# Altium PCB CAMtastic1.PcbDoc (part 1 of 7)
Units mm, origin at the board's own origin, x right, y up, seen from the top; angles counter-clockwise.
Board outline 150.22 x 135.24 mm, 5 copper layers (Top Layer, Layer 1, Mid-Layer 1, Layer 2, Bottom Layer), stack 0.461 mm thick; 0 components, 362 nets, 2885 pads, 0 vias.
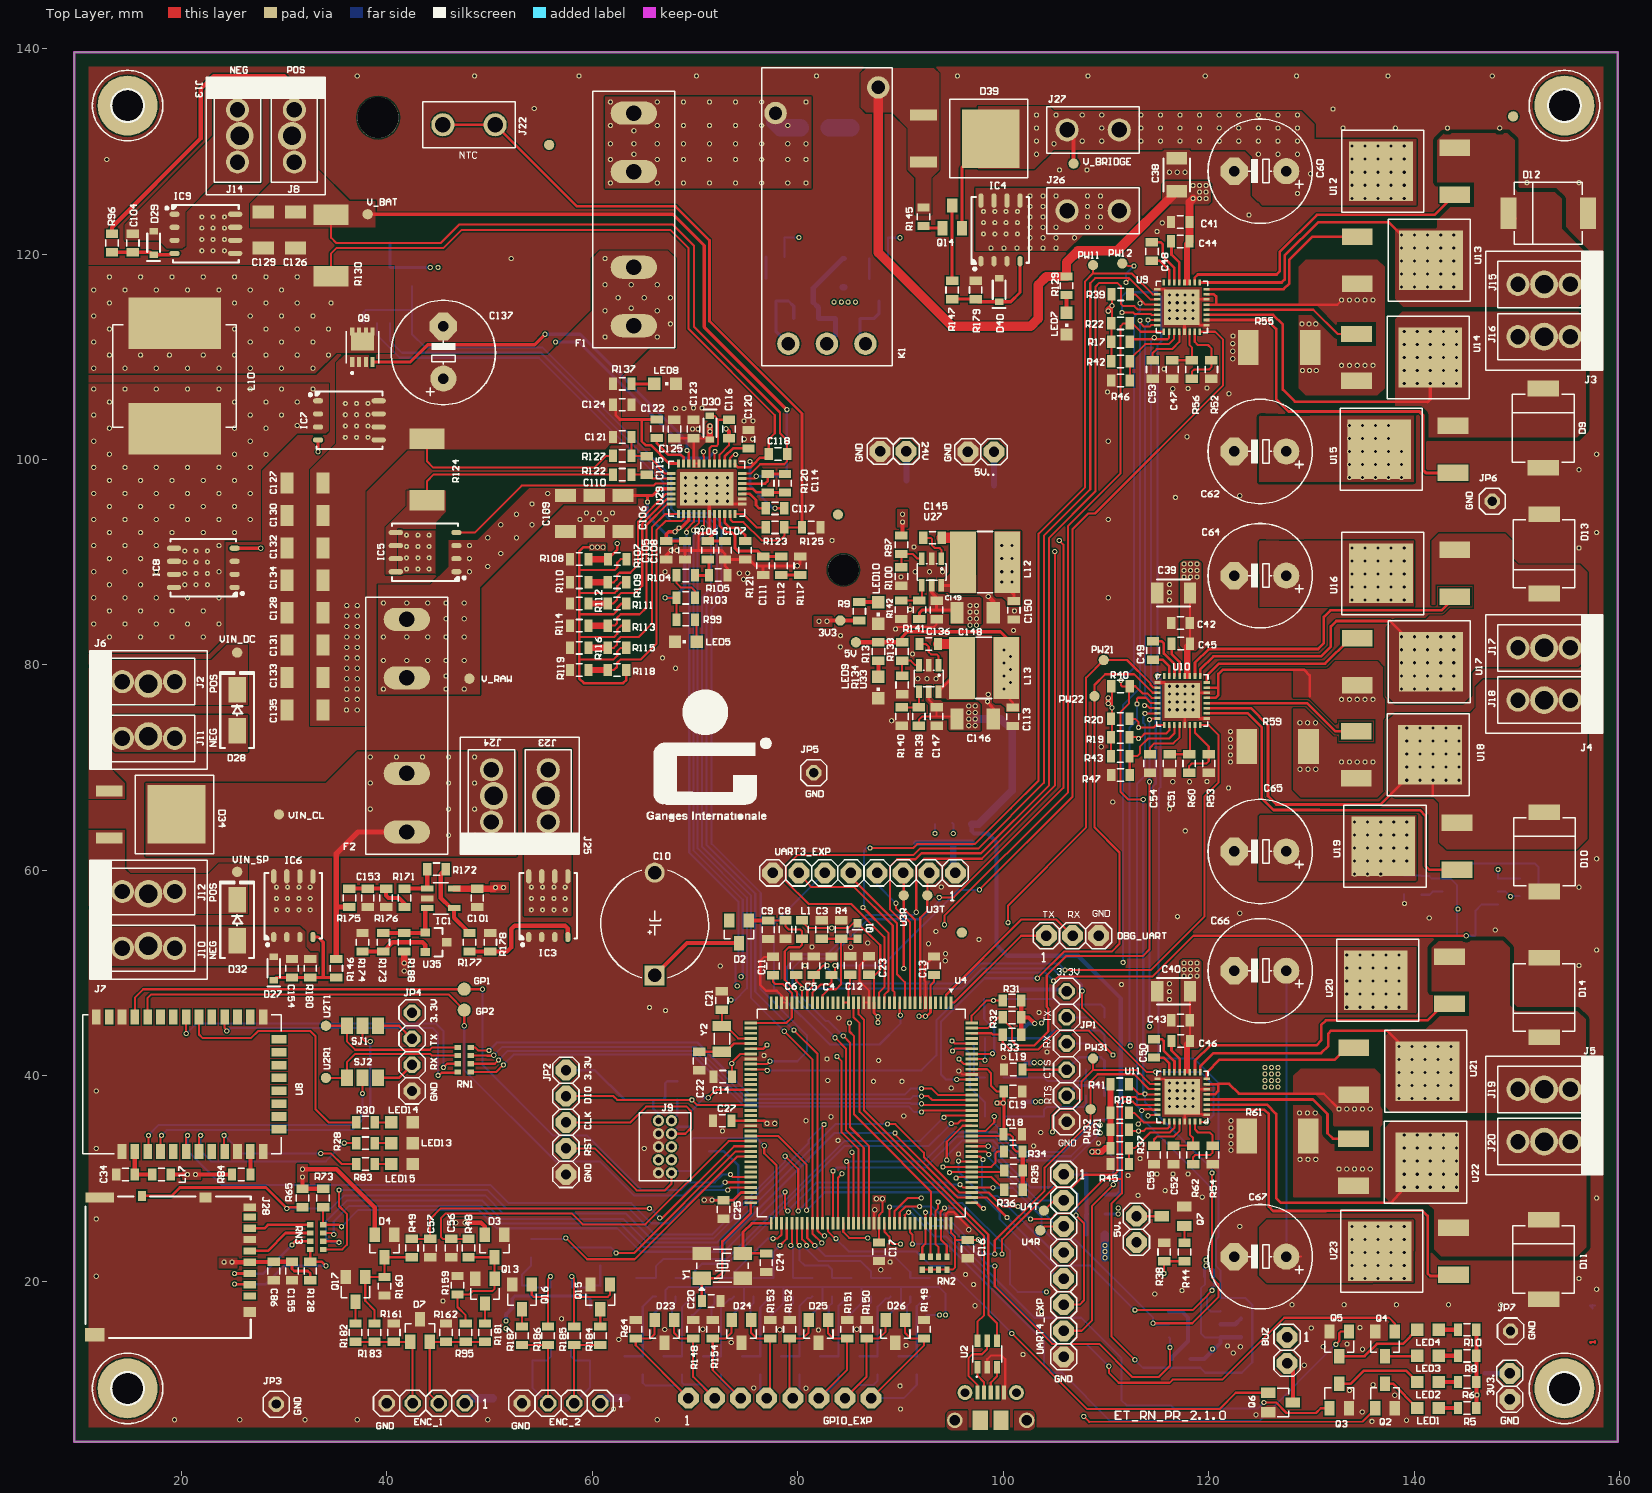
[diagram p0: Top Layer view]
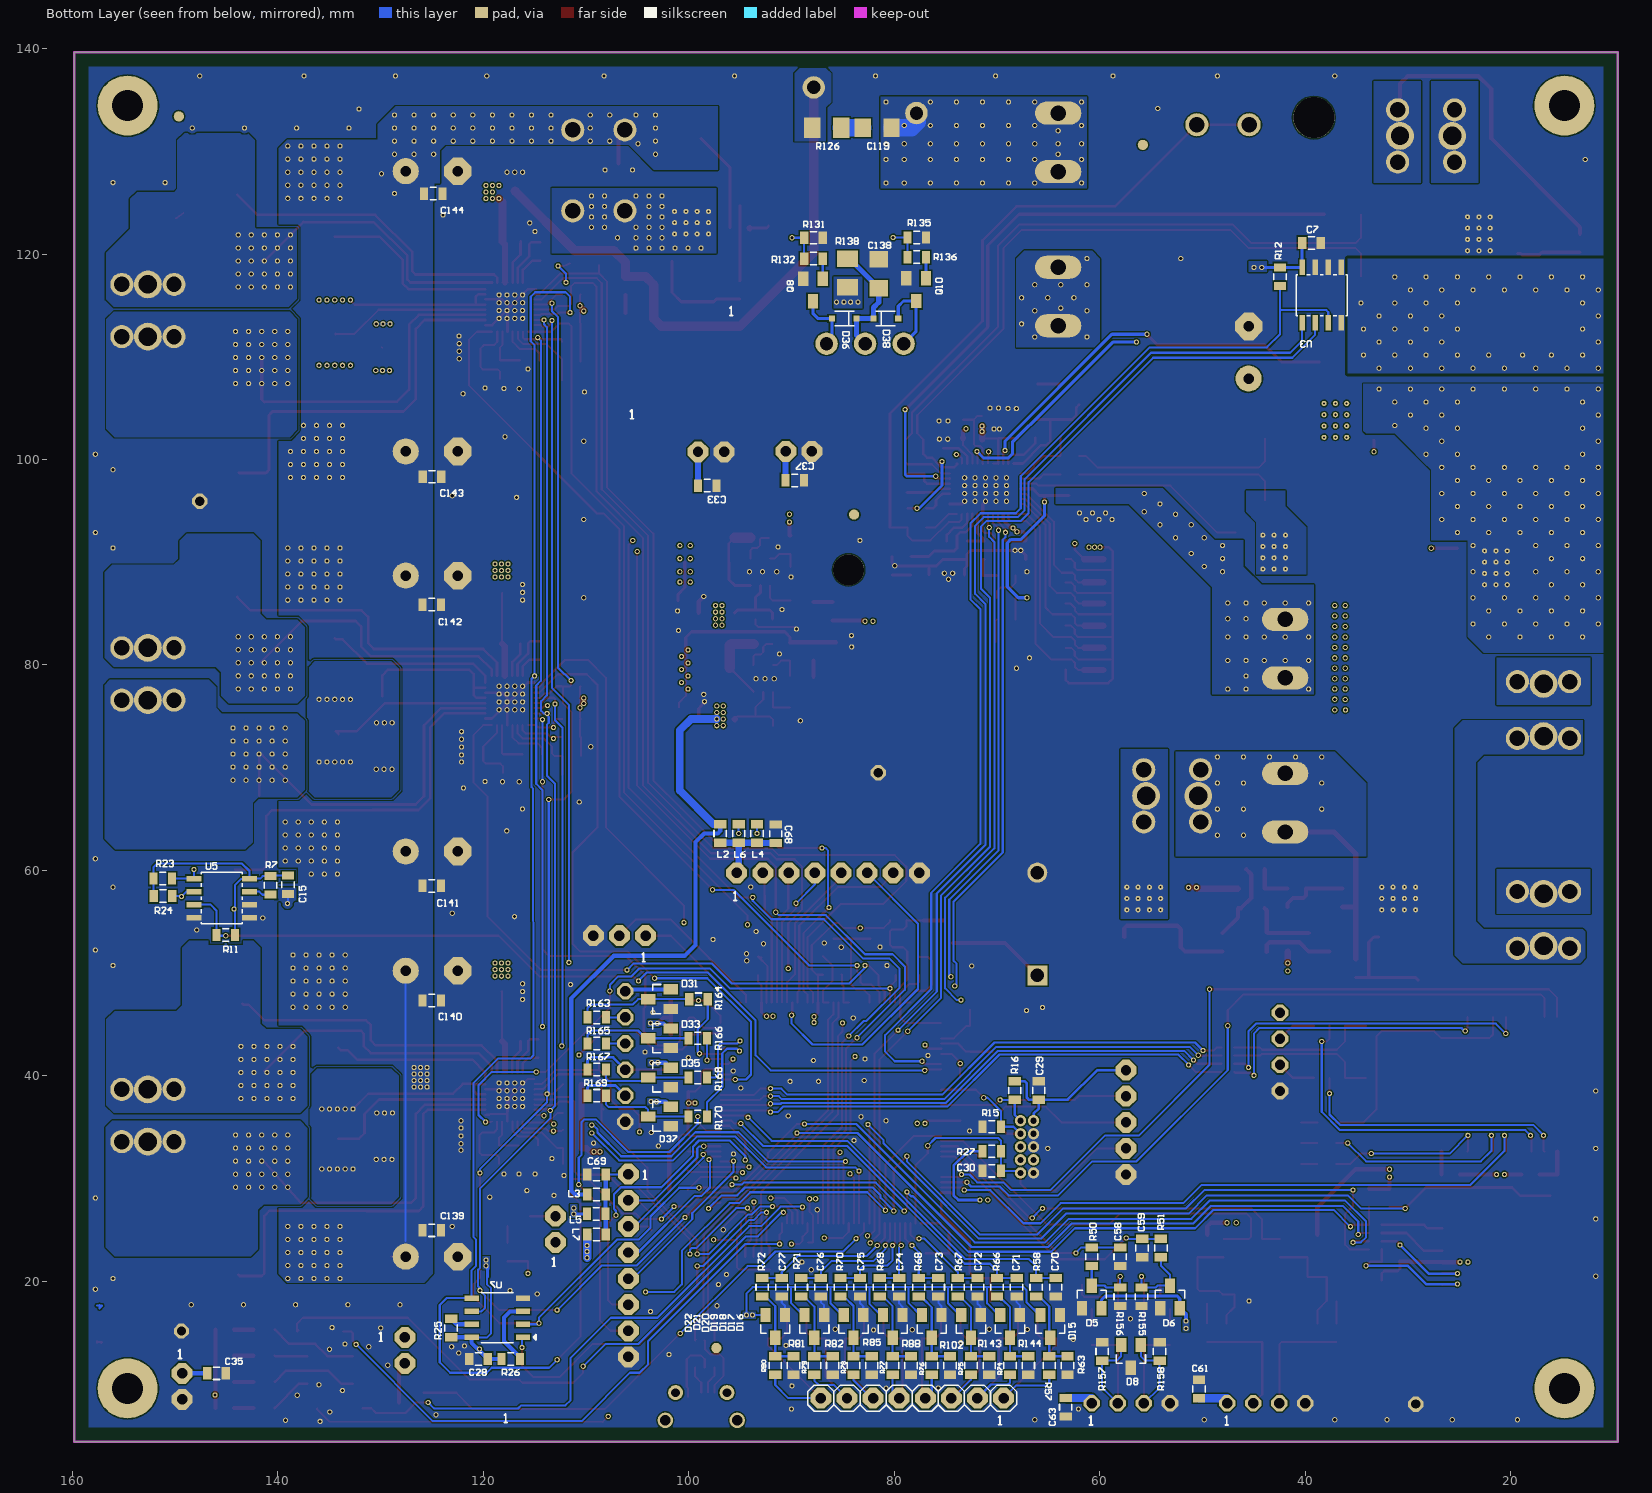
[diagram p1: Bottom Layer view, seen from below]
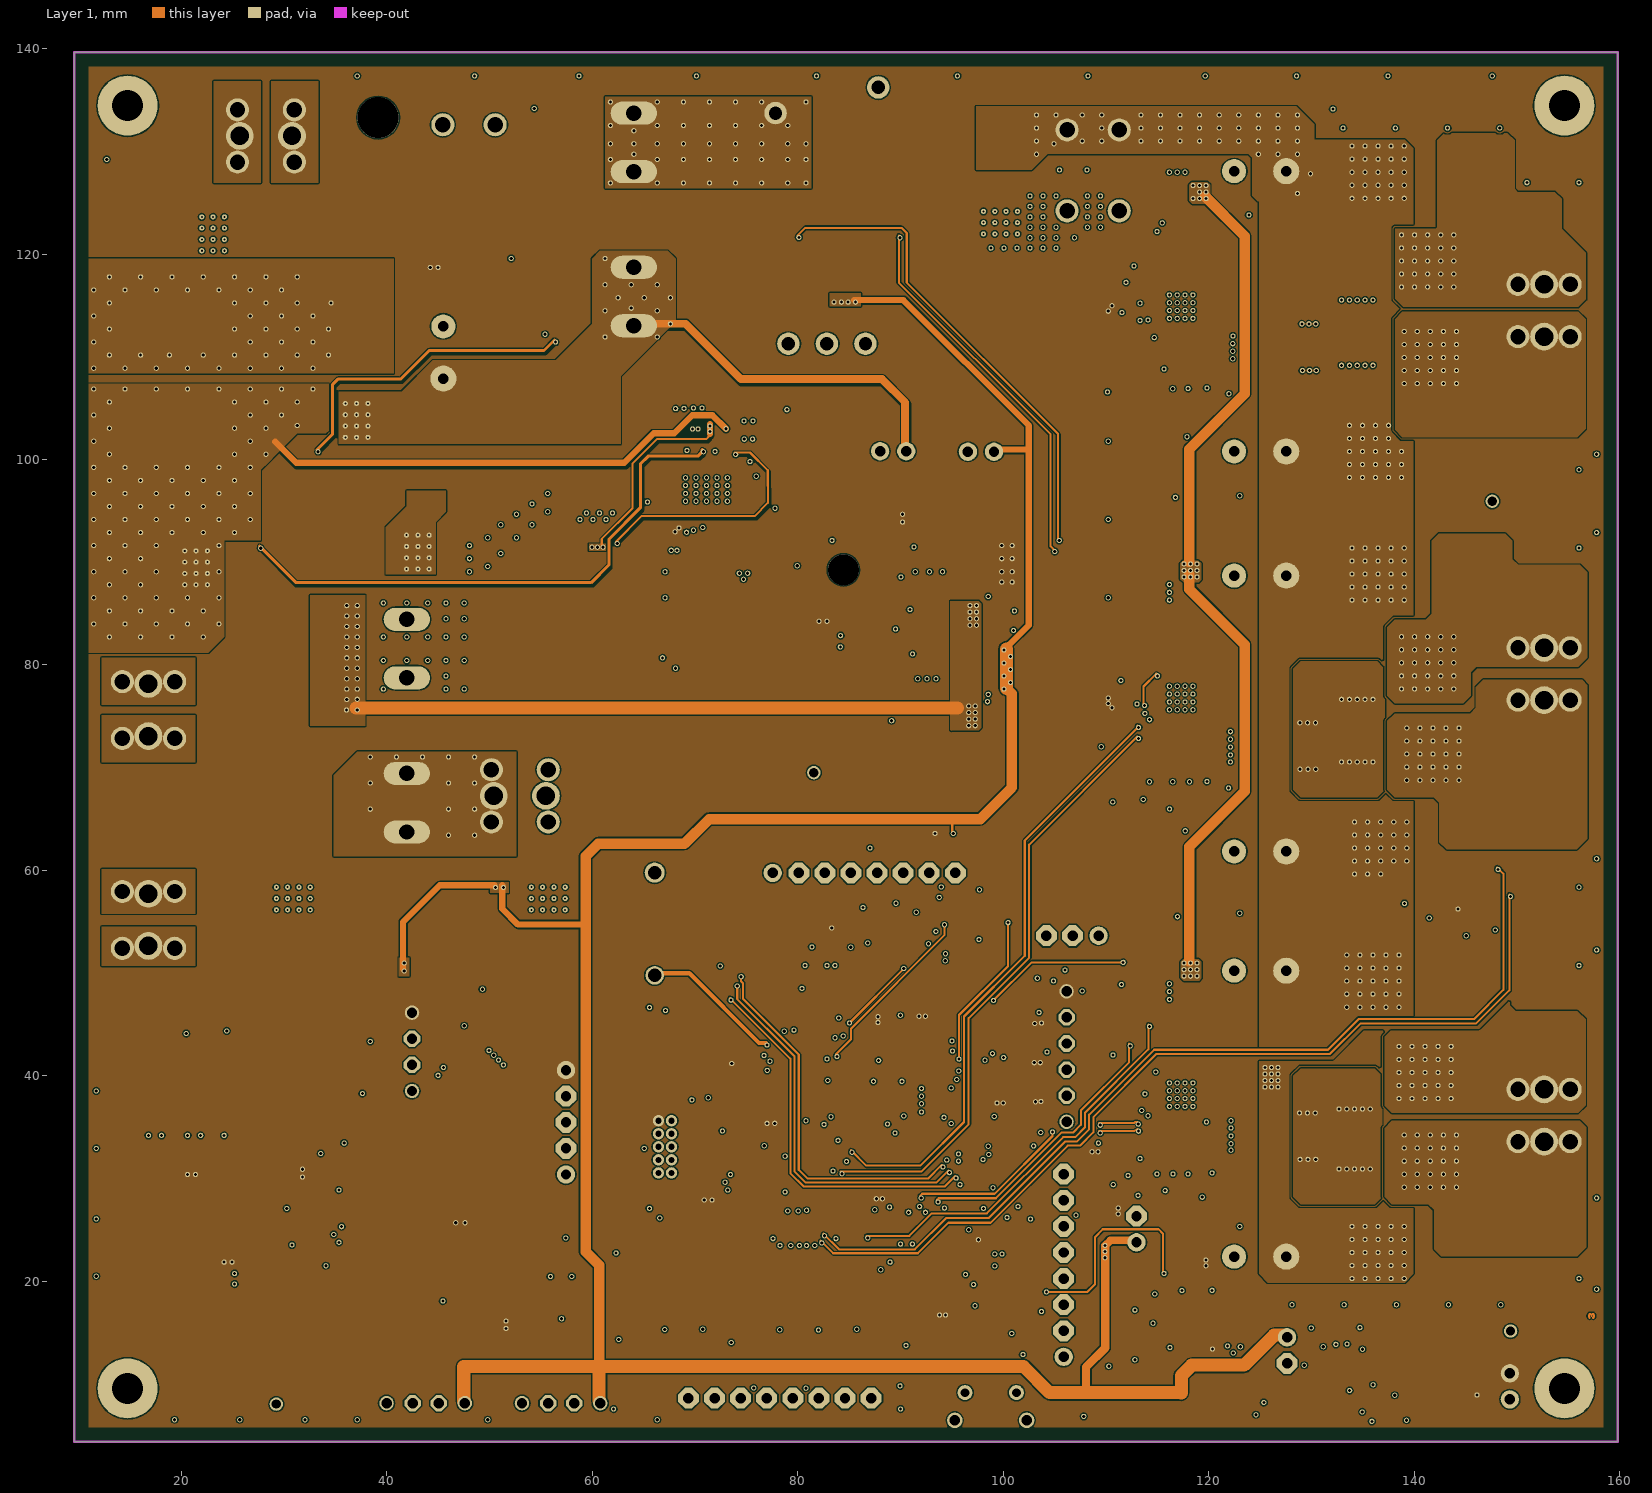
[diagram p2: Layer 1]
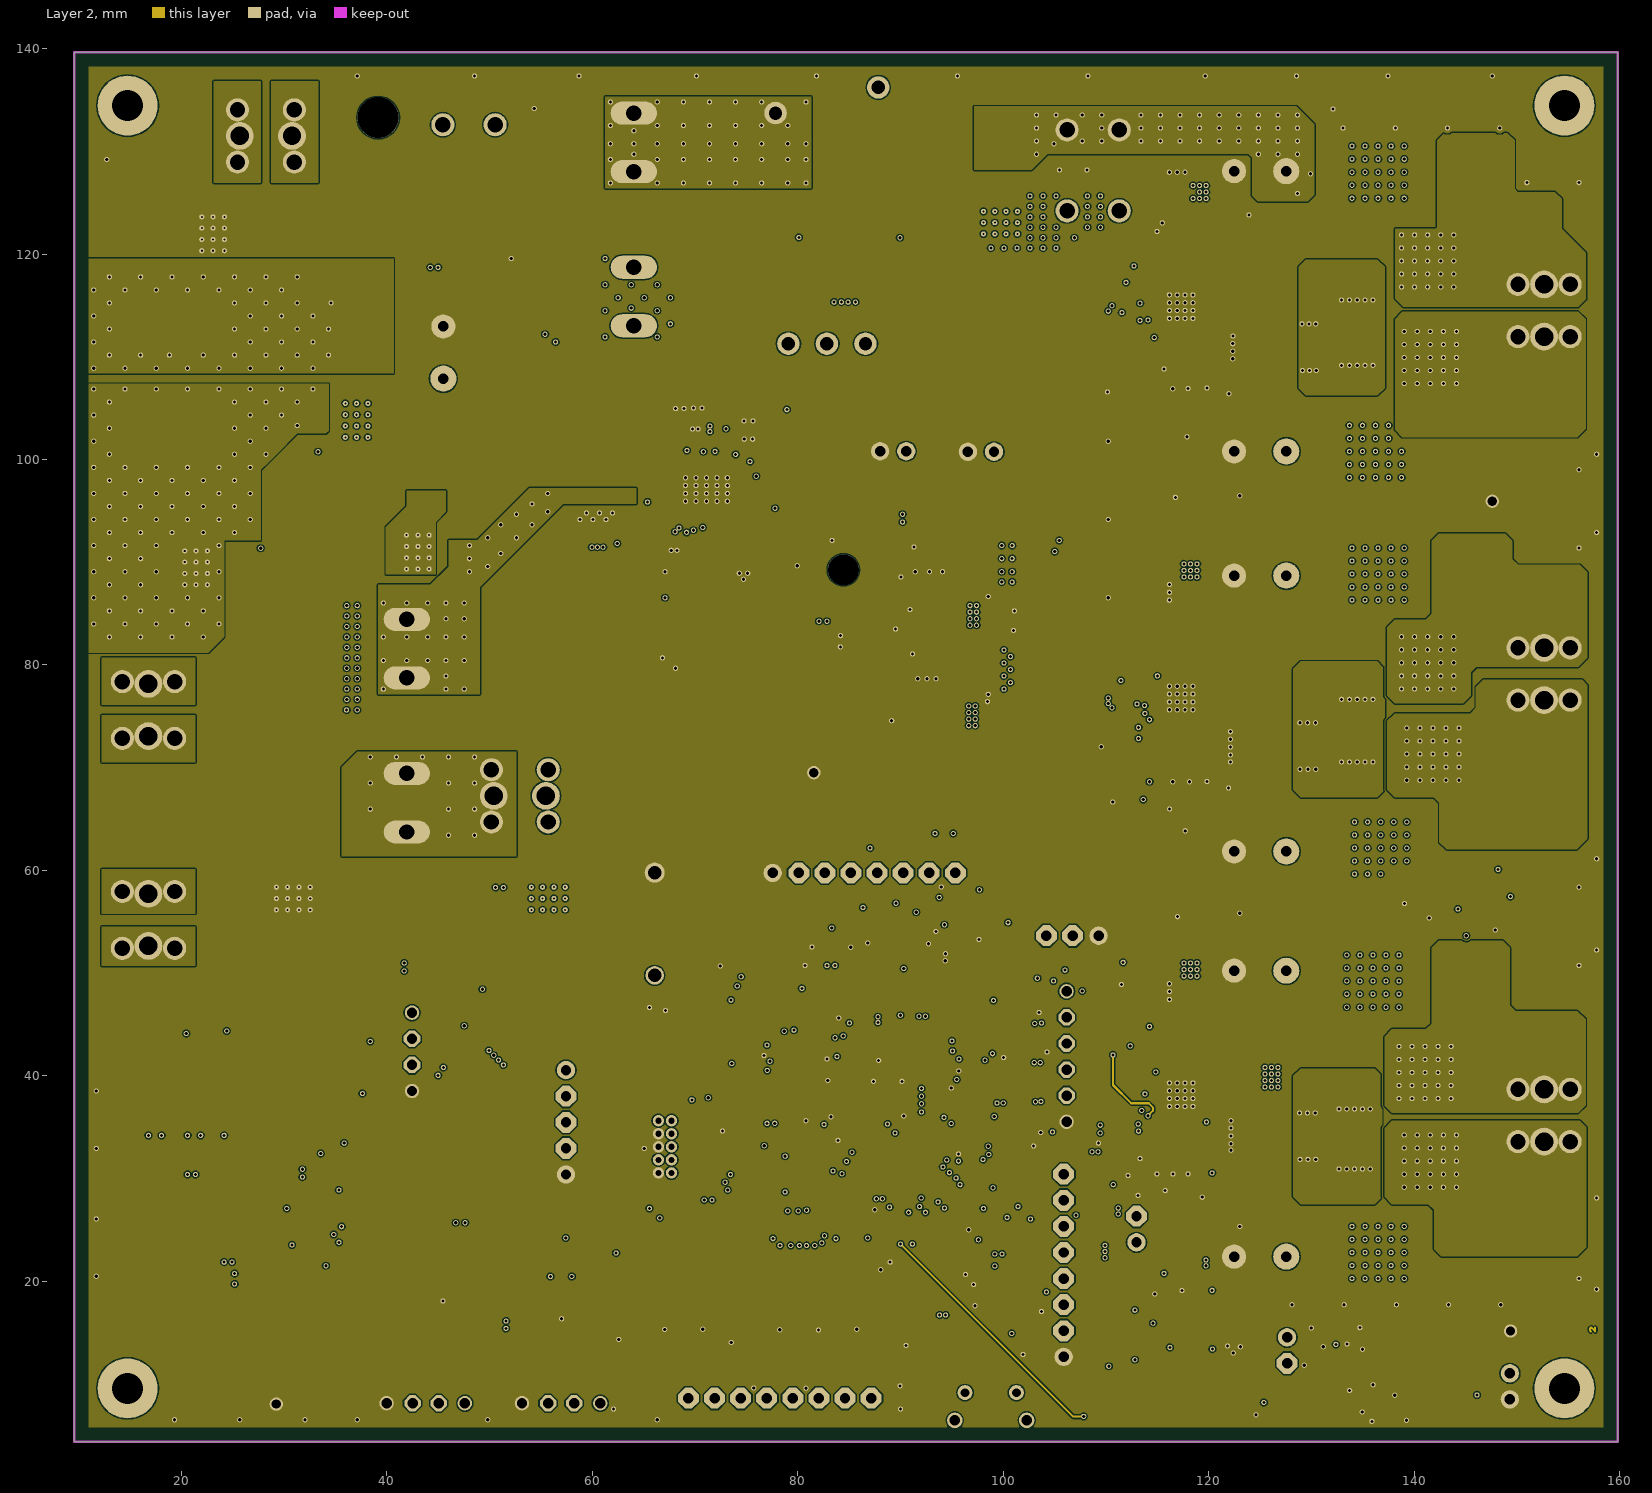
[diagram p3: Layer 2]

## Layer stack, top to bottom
Top Solder: solder mask 0.0102, Solder Resist, Dk 3.5
Top Layer: signal copper 0.0356
Dielectric 2: prepreg 0.0711, PP-006, Dk 4.1
Layer 1: signal copper 0.035
Dielectric 3: prepreg 0.0711, PP-006, Dk 4.1
Mid-Layer 1: signal copper 0.0356
Dielectric 4: prepreg 0.0711, PP-006, Dk 4.1
Layer 2: signal copper 0.035
Dielectric 5: prepreg 0.0711, PP-006, Dk 4.1
Bottom Layer: signal copper 0.0356
Bottom Solder: solder mask 0.0102, Solder Resist, Dk 3.5

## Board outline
9.571,4.394 159.794,4.394 159.794,139.632 9.571,139.632

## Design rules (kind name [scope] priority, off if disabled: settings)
Clearance [All] p1: gap=0.127 ignorepadtopadclearanceinfootprint=FALSE
HoleSize [All] p1: absolutevalues=TRUE maxlimit=4 minlimit=0.025 maxpercent=80.000 minpercent=20.000
HoleToHoleClearance [All] p1: gap=0.2 allowstackedmicrovias=TRUE
MinimumSolderMaskSliver [All] p1: minsoldermaskwidth=0
PolygonConnect CAM_PolygonConnect_$Net220 [InNet('$Net220')] p1: connectstyle=Direct reliefconductorwidth=0.254 reliefentries=4 polygonreliefangle="90 Angle" airgapwidth=0.254
PolygonConnect CAM_PolygonConnect_$Net200 [InNet('$Net200')] p2: connectstyle=Direct reliefconductorwidth=0.254 reliefentries=4 polygonreliefangle="90 Angle" airgapwidth=0.254
PolygonConnect CAM_PolygonConnect_$Net123 [InNet('$Net123')] p3: connectstyle=Direct reliefconductorwidth=0.254 reliefentries=4 polygonreliefangle="90 Angle" airgapwidth=0.254
PolygonConnect CAM_PolygonConnect_$Net124 [InNet('$Net124')] p4: connectstyle=Direct reliefconductorwidth=0.254 reliefentries=4 polygonreliefangle="90 Angle" airgapwidth=0.254
PolygonConnect CAM_PolygonConnect_$Net1 [InNet('$Net1')] p5: connectstyle=Direct reliefconductorwidth=0.254 reliefentries=4 polygonreliefangle="90 Angle" airgapwidth=0.254
PolygonConnect CAM_PolygonConnect_$Net5 [InNet('$Net5')] p6: connectstyle=Direct reliefconductorwidth=0.254 reliefentries=4 polygonreliefangle="90 Angle" airgapwidth=0.254
PolygonConnect CAM_PolygonConnect_$Net100 [InNet('$Net100')] p7: connectstyle=Direct reliefconductorwidth=0.254 reliefentries=4 polygonreliefangle="90 Angle" airgapwidth=0.254
PolygonConnect CAM_PolygonConnect_$Net19 [InNet('$Net19')] p8: connectstyle=Direct reliefconductorwidth=0.254 reliefentries=4 polygonreliefangle="90 Angle" airgapwidth=0.254
PolygonConnect CAM_PolygonConnect_$Net116 [InNet('$Net116')] p9: connectstyle=Direct reliefconductorwidth=0.254 reliefentries=4 polygonreliefangle="90 Angle" airgapwidth=0.254
PolygonConnect CAM_PolygonConnect_$Net6 [InNet('$Net6')] p10: connectstyle=Direct reliefconductorwidth=0.254 reliefentries=4 polygonreliefangle="90 Angle" airgapwidth=0.254
PolygonConnect CAM_PolygonConnect_$Net3 [InNet('$Net3')] p11: connectstyle=Direct reliefconductorwidth=0.254 reliefentries=4 polygonreliefangle="90 Angle" airgapwidth=0.254
PolygonConnect CAM_PolygonConnect_$Net7 [InNet('$Net7')] p12: connectstyle=Direct reliefconductorwidth=0.254 reliefentries=4 polygonreliefangle="90 Angle" airgapwidth=0.254
PolygonConnect CAM_PolygonConnect_$Net9 [InNet('$Net9')] p13: connectstyle=Direct reliefconductorwidth=0.254 reliefentries=4 polygonreliefangle="90 Angle" airgapwidth=0.254
PolygonConnect CAM_PolygonConnect_$Net8 [InNet('$Net8')] p14: connectstyle=Direct reliefconductorwidth=0.254 reliefentries=4 polygonreliefangle="90 Angle" airgapwidth=0.254
PolygonConnect CAM_PolygonConnect_$Net157 [InNet('$Net157')] p15: connectstyle=Direct reliefconductorwidth=0.254 reliefentries=4 polygonreliefangle="90 Angle" airgapwidth=0.254
PolygonConnect CAM_PolygonConnect_$Net80 [InNet('$Net80')] p16: connectstyle=Direct reliefconductorwidth=0.254 reliefentries=4 polygonreliefangle="90 Angle" airgapwidth=0.254
PolygonConnect CAM_PolygonConnect_$Net156 [InNet('$Net156')] p17: connectstyle=Direct reliefconductorwidth=0.254 reliefentries=4 polygonreliefangle="90 Angle" airgapwidth=0.254
PolygonConnect CAM_PolygonConnect_$Net158 [InNet('$Net158')] p18: connectstyle=Direct reliefconductorwidth=0.254 reliefentries=4 polygonreliefangle="90 Angle" airgapwidth=0.254
PolygonConnect CAM_PolygonConnect_$Net102 [InNet('$Net102')] p19: connectstyle=Direct reliefconductorwidth=0.254 reliefentries=4 polygonreliefangle="90 Angle" airgapwidth=0.254
PolygonConnect CAM_PolygonConnect_$Net101 [InNet('$Net101')] p20: connectstyle=Direct reliefconductorwidth=0.254 reliefentries=4 polygonreliefangle="90 Angle" airgapwidth=0.254
PolygonConnect CAM_PolygonConnect_$Net103 [InNet('$Net103')] p21: connectstyle=Direct reliefconductorwidth=0.254 reliefentries=4 polygonreliefangle="90 Angle" airgapwidth=0.254
PolygonConnect CAM_PolygonConnect_$Net111 [InNet('$Net111')] p22: connectstyle=Direct reliefconductorwidth=0.254 reliefentries=4 polygonreliefangle="90 Angle" airgapwidth=0.254
PolygonConnect CAM_PolygonConnect_$Net2 [InNet('$Net2')] p23: connectstyle=Direct reliefconductorwidth=0.254 reliefentries=4 polygonreliefangle="90 Angle" airgapwidth=0.254
PolygonConnect CAM_PolygonConnect_$Net107 [InNet('$Net107')] p24: connectstyle=Direct reliefconductorwidth=0.254 reliefentries=4 polygonreliefangle="90 Angle" airgapwidth=0.254
PolygonConnect CAM_PolygonConnect_$Net10 [InNet('$Net10')] p25: connectstyle=Direct reliefconductorwidth=0.254 reliefentries=4 polygonreliefangle="90 Angle" airgapwidth=0.254
PolygonConnect CAM_PolygonConnect_$Net117 [InNet('$Net117')] p26: connectstyle=Direct reliefconductorwidth=0.254 reliefentries=4 polygonreliefangle="90 Angle" airgapwidth=0.254
PolygonConnect CAM_PolygonConnect_$Net160 [InNet('$Net160')] p27: connectstyle=Direct reliefconductorwidth=0.254 reliefentries=4 polygonreliefangle="90 Angle" airgapwidth=0.254
PolygonConnect CAM_PolygonConnect_$Net109 [InNet('$Net109')] p28: connectstyle=Direct reliefconductorwidth=0.254 reliefentries=4 polygonreliefangle="90 Angle" airgapwidth=0.254
PolygonConnect CAM_PolygonConnect_$Net105 [InNet('$Net105')] p29: connectstyle=Direct reliefconductorwidth=0.254 reliefentries=4 polygonreliefangle="90 Angle" airgapwidth=0.254
PolygonConnect CAM_PolygonConnect_$Net106 [InNet('$Net106')] p30: connectstyle=Direct reliefconductorwidth=0.254 reliefentries=4 polygonreliefangle="90 Angle" airgapwidth=0.254
PolygonConnect CAM_PolygonConnect_$Net0 [InNet('$Net0')] p31: connectstyle=Direct reliefconductorwidth=0.254 reliefentries=4 polygonreliefangle="90 Angle" airgapwidth=0.254
PolygonConnect CAM_PolygonConnect_$Net4 [InNet('$Net4')] p32: connectstyle=Direct reliefconductorwidth=0.254 reliefentries=4 polygonreliefangle="90 Angle" airgapwidth=0.254
PolygonConnect CAM_PolygonConnect_$Net110 [InNet('$Net110')] p33: connectstyle=Direct reliefconductorwidth=0.254 reliefentries=4 polygonreliefangle="90 Angle" airgapwidth=0.254
PolygonConnect [All] p34: connectstyle=Relief reliefconductorwidth=0.254 reliefentries=4 polygonreliefangle="90 Angle" airgapwidth=0.254
RoutingVias [All] p1: holewidth=0.711 width=1.27 viastyle="Through Hole" minholewidth=0.711 minwidth=1.27 maxholewidth=0.711 maxwidth=1.27
SilkToSolderMaskClearance [IsPad] p1: minsilkscreentomaskgap=0 clearancetoexposedcopper=TRUE
SolderMaskExpansion [All] p1: expansion=0.102
Width [All] p1: maxlimit=2.54 minlimit=0.127 preferedwidth=0.254 midlayer1_minwidth=0.254 midlayer1_maxwidth=0.254 minimp=50.000000 maximp=50.000000 favimp=50.000000
26 further rules are at their usual default settings.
